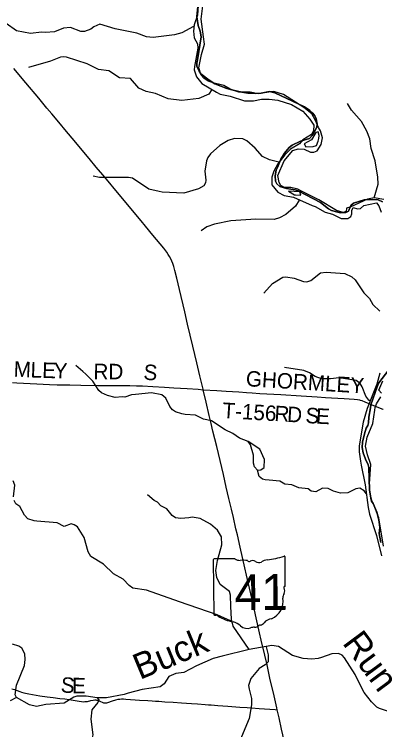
# Model space of a CAD drawing. Extents: x -51392 to 1635000, y 156707 to 696232.
# Drawn here: x 147584 to 154673, y 434151 to 448029 of the extents above; entities that cross this region are included whole.
import ezdxf

# ---------------------------------------------------------------- set-up
doc = ezdxf.new("R2010")
doc.units = 0
for name, color, linetype in [('GM_X_Major_River', 7, 'Continuous'), ('GM_X_Minor_River', 7, 'Continuous'), ('GM_X_Minor_River_Text', 7, 'Continuous'), ('GM_X_State_Route', 7, 'Continuous'), ('GM_X_State_Shield', 7, 'Continuous'), ('GM_X_Township', 7, 'Continuous'), ('GM_X_Township_Road', 7, 'Continuous'), ('GM_X_Township_Road_Text', 7, 'Continuous')]:
    doc.layers.add(name, color=color, linetype=linetype)

msp = doc.modelspace()

# ---------------------------------------------------------------- linework, layer by layer
at = {"layer": 'GM_X_Major_River'}
for points in [[(151161, 448293), (151137, 448013), (151073, 447827), (151064, 447703), (151077, 447572), (151136, 447454), (151145, 447373), (151080, 447017), (151077, 446949), (151118, 446816), (151225, 446689), (151506, 446516), (151578, 446481), (151770, 446440), (152051, 446349), (152222, 446348), (152378, 446380), (152532, 446385), (152700, 446364), (152964, 446279), (153183, 446151), (153318, 445997), (153393, 445881), (153390, 445766), (153349, 445698), (153180, 445594), (153116, 445514), (152944, 445411), (152831, 445300), (152700, 445125), (152618, 444989), (152598, 444925), (152581, 444871), (152578, 444719), (152699, 444577), (152822, 444512), (153000, 444479), (153361, 444321), (153421, 444299), (153615, 444189), (153756, 444151), (153924, 444070), (154058, 444065), (154111, 444104), (154133, 444158), (154130, 444226), (154158, 444284), (154244, 444257), (154304, 444261), (154365, 444321), (154610, 444371), (154659, 444312), (154704, 444189)], [(154752, 444434), (154566, 444467), (154438, 444444), (154116, 444295), (154028, 444265), (154025, 444201), (153963, 444182), (153837, 444223), (153495, 444430), (153154, 444595), (153086, 444636), (152952, 444671), (152826, 444670), (152754, 444711), (152720, 444768), (152698, 444904), (152818, 445186), (152988, 445387), (153089, 445420), (153205, 445413), (153330, 445354), (153393, 445353), (153461, 445381), (153540, 445502), (153567, 445634), (153526, 445771), (153485, 445832), (153430, 445972), (153355, 446097), (153200, 446223), (152810, 446475), (152618, 446531), (152568, 446523), (152313, 446487), (152159, 446517), (151939, 446518), (151773, 446574), (151649, 446645), (151570, 446668), (151464, 446693), (151348, 446732), (151262, 446791), (151207, 446851), (151166, 446992), (151214, 447250), (151274, 447450), (151253, 447593), (151210, 447932), (151264, 448353)], [(153432, 445738), (153351, 445594), (153210, 445515), (153239, 445457), (153381, 445462), (153450, 445483), (153479, 445569)], [(153479, 445569), (153495, 445617), (153500, 445679), (153482, 445749), (153432, 445738)], [(152907, 444596), (153019, 444528), (153038, 444528)], [(153038, 444528), (153141, 444523), (153125, 444582), (152907, 444596)], [(154679, 441066), (154619, 440856), (154430, 440379), (154356, 440115), (154274, 439658), (154273, 439544), (154299, 439357), (154312, 439281), (154393, 438904), (154447, 438462), (154476, 438335), (154613, 437919), (154708, 437524)], [(154711, 440681), (154658, 440736), (154735, 440919)], [(154747, 437710), (154660, 438258), (154560, 438511), (154521, 438594), (154480, 438768), (154476, 438923), (154503, 439296), (154434, 439481), (154400, 439651), (154431, 439823), (154542, 440093), (154578, 440349), (154587, 440401), (154611, 440475), (154695, 440611)]]:
    msp.add_lwpolyline(points, dxfattribs=at)
at = {"layer": 'GM_X_Minor_River'}
for points in [[(151063, 447790), (150835, 447671), (150695, 447630), (150278, 447581), (150146, 447592), (149960, 447664), (149540, 447750), (149245, 447835), (149124, 447789), (149067, 447740), (148947, 447695), (148873, 447697), (148673, 447775), (148539, 447760), (148364, 447688), (148192, 447675), (148110, 447680), (147901, 447657), (147627, 447706), (147424, 447848)], [(151415, 446572), (151358, 446477), (151163, 446395), (150836, 446357), (150568, 446386), (150322, 446494), (150140, 446534), (150001, 446597), (149840, 446783), (149622, 446797), (149421, 446935), (149217, 446955), (148997, 447065), (148598, 447196), (148534, 447201), (148482, 447199), (148289, 447119), (147857, 447000)], [(154566, 444467), (154643, 444733), (154640, 444872), (154587, 445185), (154507, 445426), (154482, 445615), (154423, 445764), (154319, 445947), (154129, 446169), (154050, 446298)], [(152719, 445160), (152538, 445206), (152402, 445271), (152258, 445429), (152095, 445573), (152017, 445614), (151859, 445621), (151736, 445584), (151575, 445481), (151390, 445320), (151337, 445250), (151310, 445187), (151280, 444988), (151303, 444814), (151296, 444760), (151262, 444704), (151157, 444645), (150872, 444561), (150454, 444578), (150394, 444589), (150196, 444637), (149879, 444850), (149799, 444865), (149445, 444862), (149235, 444863), (149113, 444890)], [(153114, 444426), (153039, 444304), (152855, 444147), (152732, 444080), (152624, 444049), (152268, 444052), (151787, 444020), (151466, 443958), (151319, 443907), (151208, 443830)], [(152425, 442621), (152595, 442808), (152794, 442929), (152851, 442938), (153015, 442911), (153196, 442845), (153262, 442842), (153335, 442866), (153526, 443013), (153638, 443028), (153997, 442999), (154136, 442933), (154196, 442875), (154364, 442627), (154475, 442515), (154542, 442401), (154673, 442273)], [(154418, 438729), (154370, 438787), (154289, 438836), (154210, 438821), (154053, 438748), (153915, 438741), (153779, 438776), (153674, 438827), (153566, 438834), (153433, 438765), (153347, 438780), (153283, 438821), (153107, 438842), (152967, 438904), (152835, 438913), (152738, 438970), (152530, 438992), (152454, 438998), (152402, 439013), (152338, 439063), (152301, 439186), (152247, 439251), (152222, 439323), (152225, 439475), (152165, 439674), (152124, 439741), (151956, 439806), (151827, 439898), (151675, 439967), (151412, 440140), (151256, 440173), (151097, 440253), (150901, 440268), (150833, 440279), (150709, 440318), (150655, 440353), (150599, 440419), (150523, 440580), (150447, 440645), (150247, 440683), (149933, 440655), (149861, 440648), (149726, 440599), (149674, 440610), (149538, 440595), (149390, 440632), (149276, 440683), (149222, 440730), (149106, 440911), (148971, 441049), (148915, 441101), (148778, 441217)], [(154488, 440525), (154464, 440545), (154402, 440619), (154334, 440802), (154294, 440865), (154215, 440924), (153887, 440975), (153716, 440958), (153546, 440960), (153424, 441005), (153311, 441076), (153201, 441119), (152825, 441178)], [(152301, 439186), (152365, 439191), (152434, 439235), (152439, 439391), (152351, 439594), (152124, 439741)], [(147570, 438671), (147594, 438897), (147559, 438976)], [(152140, 435709), (151828, 436159), (151795, 436297), (151785, 436538), (151777, 436761), (151758, 436829), (151581, 436969), (151516, 437104), (151495, 437240), (151529, 437436), (151613, 437734), (151603, 437893), (151528, 438022), (151393, 438135), (151187, 438245), (151033, 438275), (150973, 438263), (150817, 438250), (150711, 438261), (150645, 438308), (150546, 438433), (150428, 438494), (150365, 438563), (150295, 438596), (150170, 438707)], [(151798, 436255), (151721, 436288), (151523, 436378), (150788, 436631), (150152, 436857), (149884, 436897), (149812, 436946), (149695, 437073), (149506, 437177), (149317, 437361), (149072, 437513), (149019, 437604), (148941, 437879), (148809, 438085), (148743, 438128), (148685, 438142), (148550, 438093), (148413, 438166), (148023, 438196), (147968, 438202), (147849, 438243), (147779, 438310), (147691, 438483), (147615, 438532), (147583, 438597)], [(154845, 434501), (154671, 434561), (154618, 434590), (154512, 434691), (154370, 434874), (154301, 435011), (154199, 435219), (153993, 435547), (153944, 435598), (153872, 435628), (153748, 435623), (153543, 435549), (153482, 435531), (153354, 435516), (153188, 435530), (152980, 435590), (152709, 435768), (152583, 435786), (152140, 435709), (151614, 435577), (151442, 435529), (151120, 435389), (150875, 435261), (150716, 435240), (150581, 435181), (150490, 435040), (150413, 434984), (150067, 434929), (149794, 434857), (149717, 434836), (149376, 434770), (149192, 434768), (148976, 434802), (148796, 434801), (148741, 434784), (148550, 434663), (148199, 434638), (148013, 434602), (147881, 434633), (147626, 434777), (147501, 434708)], [(147626, 434777), (147602, 434826), (147626, 435012), (147780, 435399), (147795, 435512), (147786, 435622), (147728, 435733), (147675, 435773), (147547, 435808)], [(152469, 435756), (152510, 435600), (152507, 435467), (152454, 435412), (152337, 435335), (152171, 435146), (152126, 435010), (152139, 434937), (152186, 434759), (152187, 434636), (152138, 434370), (151995, 434010), (151976, 433898), (151737, 433347), (151470, 433077), (151410, 433015), (151353, 432959), (151274, 432820), (151199, 432586), (151142, 432462), (151092, 432394), (150906, 432229), (150855, 432142), (150645, 431061)], [(149192, 434768), (149226, 434728), (149203, 434676), (149088, 434538), (149072, 434358), (149110, 434053), (149078, 433921), (149062, 433859), (149059, 433727), (148943, 433511), (148742, 433290), (148623, 433111), (148584, 432999), (148493, 432675), (148409, 432243), (148388, 432171), (148335, 432101), (148300, 431971), (148238, 431913), (148167, 431856), (148055, 431845), (148000, 431817), (147831, 431626), (147735, 431481)]]:
    msp.add_lwpolyline(points, dxfattribs=at)
at = {"layer": 'GM_X_State_Route'}
msp.add_lwpolyline([(152850, 433808), (152771, 434160), (152721, 434384), (152685, 434537), (152676, 434576), (152610, 434863), (152551, 435119), (152515, 435279), (152488, 435407), (152444, 435599), (152376, 435886), (152344, 436030), (152265, 436382), (152216, 436590), (152120, 437005), (152056, 437293), (151965, 437693), (151912, 437933), (151885, 438049), (151834, 438268), (151796, 438428), (151748, 438636), (151696, 438859), (151640, 439099), (151512, 439642), (151439, 439944), (151403, 440088), (151367, 440248), (151307, 440503), (151250, 440747), (151247, 440759), (151186, 441014), (151125, 441269), (151049, 441588), (150947, 442019), (150891, 442258), (150787, 442689), (150735, 442913), (150700, 443056), (150678, 443135), (150657, 443197), (150640, 443243), (150620, 443287), (150597, 443330), (150571, 443372), (150543, 443412), (150483, 443489), (150275, 443743), (150128, 443919), (150044, 444020), (149877, 444222), (149719, 444411), (149552, 444613), (149405, 444790), (149300, 444916), (149173, 445066), (149036, 445230), (148869, 445432), (148743, 445583), (148595, 445758), (148448, 445934), (148312, 446099), (148216, 446211), (148058, 446400), (147805, 446701), (147575, 446979)], dxfattribs=at)
at = {"layer": 'GM_X_State_Shield'}
for p, q in [((151445, 437445), (151455, 436388)), ((151866, 437467), (151459, 437463)), ((152842, 436950), (152837, 437502)), ((152842, 436950), (152842, 436950))]:
    msp.add_line(p, q, dxfattribs=at)
for centre, radius, start, end in [((151461, 437447), 16.1, 98.6686, 188.6686), ((151962, 437591), 156, 232.1581, 271.6504), ((152021, 436875), 562, 81.0252, 95.5268), ((152143, 437459), 45.1, 220.3306, 297.6409), ((152210, 437338), 93.8, 55.0052, 119.6797), ((152532, 437151), 297, 97.8847, 121.3074), ((152327, 438912), 1476, 276.383, 289.445), ((152821, 437504), 15.5, 352.4006, 98.2765), ((152330, 437506), 113, 234.3948, 295.3667), ((152839, 436909), 24, 108.4825, 210.8755), ((152687, 436838), 144, 340.5715, 24.1881), ((152825, 436947), 16.6, 290.1424, 8.2727), ((152900, 436719), 105, 137.345, 187.4681), ((152431, 436644), 369, 292.8474, 9.5244), ((151471, 436386), 16.3, 172.4969, 258.8452), ((151472, 436494), 124, 267.8775, 281.1424), ((151499, 436328), 44.8, 30.2869, 93.8103), ((152056, 437282), 1066, 240.9515, 257.737), ((151751, 435916), 334, 47.7227, 76.3745), ((152349, 436149), 31.8, 66.2903, 133.187), ((152334, 436294), 119, 283.4117, 323.8157), ((152592, 436102), 202, 94.9417, 143.1153), ((152108, 436328), 212, 231.2389, 286.8304), ((152233, 435964), 174, 86.2337, 111.7485), ((152246, 436250), 113, 269.3156, 316.0878)]:
    msp.add_arc(centre, radius, start, end, dxfattribs=at)
at = {"layer": 'GM_X_Township'}
for points in [[(151158, 448321), (151127, 447982), (151151, 447810), (151191, 447703), (151212, 447593), (151139, 447144), (151123, 447082), (151124, 447026), (151168, 446924), (151204, 446874), (151366, 446751), (151476, 446680), (151710, 446592), (151828, 446557), (151999, 446516), (152115, 446498), (152271, 446494), (152373, 446501), (152536, 446529), (152638, 446508), (153212, 446236), (153320, 446164), (153374, 446113), (153418, 446061), (153442, 446003), (153460, 445895), (153451, 445839), (153397, 445727), (153363, 445675), (153312, 445617), (153138, 445567), (152975, 445492), (152917, 445446), (152825, 445334), (152754, 445216), (152688, 445056), (152667, 445004), (152647, 444897), (152655, 444795), (152677, 444741), (152733, 444689), (152867, 444648), (153031, 444626), (153091, 444602), (153523, 444376), (153683, 444253), (153737, 444225), (153859, 444188), (153915, 444180), (154017, 444184), (154068, 444210), (154116, 444320), (154166, 444364), (154375, 444427), (154535, 444439), (154643, 444428), (154727, 444394)], [(154727, 444394), (154643, 444428), (154535, 444439), (154375, 444427), (154166, 444364), (154116, 444320), (154068, 444210), (154017, 444184), (153915, 444180), (153859, 444188), (153737, 444225), (153683, 444253), (153523, 444376), (153091, 444602), (153031, 444626), (152867, 444648), (152733, 444689), (152677, 444741), (152655, 444795), (152647, 444897), (152667, 445004), (152688, 445056), (152754, 445216), (152825, 445334), (152917, 445446), (152975, 445492), (153138, 445567), (153312, 445617), (153363, 445675), (153397, 445727), (153451, 445839), (153460, 445895), (153442, 446003), (153418, 446061), (153374, 446113), (153320, 446164), (153212, 446236), (152638, 446508), (152536, 446529), (152373, 446501), (152271, 446494), (152115, 446498), (151999, 446516), (151828, 446557), (151710, 446592), (151476, 446680), (151366, 446751), (151204, 446874), (151168, 446924), (151124, 447026), (151123, 447082), (151139, 447144), (151212, 447593), (151191, 447703), (151151, 447810), (151127, 447982), (151158, 448321)], [(154852, 441132), (154659, 440882), (154622, 440804), (154501, 440452), (154492, 440394), (154464, 440215), (154456, 440105), (154442, 440051), (154409, 439999), (154377, 439893), (154342, 439731), (154332, 439625), (154352, 439519), (154395, 439398), (154453, 439290), (154463, 439238), (154474, 438807), (154503, 438641), (154515, 438586), (154545, 438536), (154615, 438372), (154652, 438247), (154666, 438183), (154674, 438075), (154666, 437959), (154695, 437782)], [(154695, 437782), (154666, 437959), (154674, 438075), (154666, 438183), (154652, 438247), (154615, 438372), (154545, 438536), (154515, 438586), (154503, 438641), (154474, 438807), (154463, 439238), (154453, 439290), (154395, 439398), (154352, 439519), (154332, 439625), (154342, 439731), (154377, 439893), (154409, 439999), (154442, 440051), (154456, 440105), (154464, 440215), (154492, 440394), (154501, 440452), (154622, 440804), (154659, 440882), (154852, 441132)]]:
    msp.add_lwpolyline(points, dxfattribs=at)
at = {"layer": 'GM_X_Township_Road'}
for points in [[(147549, 440885), (147631, 440879), (148024, 440859), (148269, 440846), (148417, 440842), (148663, 440838), (148876, 440835), (149204, 440831), (149483, 440829), (149647, 440828), (149827, 440827), (149958, 440824), (150073, 440819), (150269, 440806), (150499, 440793), (150679, 440782), (150941, 440767), (151153, 440754), (151250, 440747)], [(151250, 440747), (151513, 440730), (151694, 440719), (151939, 440702), (152086, 440693), (152201, 440686), (152348, 440676), (152757, 440651), (153150, 440628), (153461, 440608), (153624, 440598), (153739, 440592), (153985, 440576), (154181, 440562), (154246, 440556), (154279, 440549), (154297, 440544)], [(154297, 440544), (154327, 440535), (154388, 440512), (154508, 440462)], [(154508, 440462), (154555, 440443), (154737, 440368), (154743, 440366)], [(147537, 434944), (147585, 434930), (147692, 434890), (147723, 434880), (147771, 434867), (147867, 434848), (148077, 434811), (148223, 434788), (148337, 434773), (148468, 434759), (148566, 434749), (148647, 434738), (148841, 434704), (148890, 434697), (148922, 434694), (148955, 434695), (148971, 434696), (149004, 434701), (149068, 434715), (149116, 434725), (149149, 434729), (149165, 434729), (149182, 434727), (149197, 434724), (149213, 434718), (149228, 434712), (149257, 434697), (149286, 434682), (149302, 434676), (149317, 434671), (149333, 434669), (149350, 434669), (149366, 434671), (149382, 434674), (149398, 434678), (149491, 434711), (149554, 434730), (149602, 434741), (149634, 434746), (149667, 434748), (149700, 434748), (149749, 434745), (149929, 434733), (150011, 434727), (150174, 434716), (150256, 434711), (150321, 434706), (150387, 434702), (150502, 434694), (150665, 434683), (150829, 434671), (151025, 434658), (151140, 434651), (151287, 434641), (151353, 434636), (151402, 434632), (151533, 434623), (151729, 434608), (151958, 434590), (152105, 434579), (152187, 434573), (152334, 434563), (152645, 434540), (152685, 434537)]]:
    msp.add_lwpolyline(points, dxfattribs=at)

# ---------------------------------------------------------------- texts
at = {"layer": 'GM_X_Minor_River_Text'}
for s, rotation, p in [('Buck', 22.538, (150019, 435114)), ('Run', 306.5354, (153936, 435830))]:
    msp.add_text(s, height=500, rotation=rotation, dxfattribs=at).set_placement(p)
at = {"layer": 'GM_X_State_Shield'}
msp.add_text('41', height=696.1, rotation=0.5385, dxfattribs=at).set_placement((151861, 436467))
at = {"layer": 'GM_X_Township_Road_Text'}
for s, rotation, p in [('M', 357.4599, (147567, 441000)), ('L', 357.9678, (147895, 440985)), ('E', 357.9706, (148120, 440977)), ('Y', 357.9696, (148344, 440970)), ('RD', 359.6403, (149119, 440951)), ('S', 355.6722, (150082, 440943)), ('GHORMLEY', 356.4191, (152070, 440816)), ('T-156', 356.3339, (151615, 440201)), ('R', 356.3781, (152624, 440140)), ('D', 356.3892, (152870, 440124)), ('S', 356.5267, (153227, 440102)), ('E', 357.1326, (153432, 440089)), ('S', 355.3093, (148477, 434877)), ('E', 359.1781, (148701, 434859))]:
    msp.add_text(s, height=300, rotation=rotation, dxfattribs=at).set_placement(p)

doc.saveas('drawing.dxf')
